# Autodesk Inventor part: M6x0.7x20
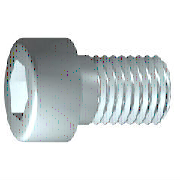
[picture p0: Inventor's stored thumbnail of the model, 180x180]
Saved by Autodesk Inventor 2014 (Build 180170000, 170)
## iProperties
Created: 2009-02
Part Number: M6x0.7x20
Material: 강철, 연강
Description: 6각머리 태핑 나사
Document SubType Name: Modeling
Standard: KS B 1003
Designer: KYOUNG IL JANG
Standards Organization: KS
Language: ko-KR
Size Designation: M 6 x 20
Categories: <MemberInstance><Categories><Category DisplayName="조임쇠" InternalName="e4da775c-781d-43d5-af7c-5136215cf5a6" Mnemonic="FSTN"><Category DisplayName="볼트" InternalN
Density: 7.86 g/cm^3
Mass: 7.48273 g
Surface Area: 7.641 cm^2
Volume: 0.952002 cm^3
Vendor: CBT Solutions
Appearance: 연마 - 진회색
Company: 한국ATC센터
IsCustomPart: 1
Author: KYOUNG IL JANG
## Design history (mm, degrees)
sketch "스케치1"
  geometry: L1 (-1.333, 0)-(20, 0); L2 (20, 0)-(20, 3); L3 (20, 3)-(2.5, 3); L4 (2.5, 3)-(1.886, 3); L5 (1.886, 3)-(0, 3); L6 (0, 3)-(0, 5); L7 (0, 5)-(-6, 5); L8 (-6, 5)-(-6, 2.887); L9 (-6, 2.887)-(-3, 2.887); L10 (-3, 2.887)-(-1.333, 0); L11 (-11.2, 0)-(25.2, 0) reference; L12 (0, -1)-(0, 6) reference; L13 (2.5, 3)-(0, 3)
  constraints: 22 end point, 6 parallel, 2 collinear, 2 perpendicular, 1 horizontal, 1 point on line
  dimensions: "d1" = 17.5 distance from line of L3.end L2 (= GEL); "d2" = 0.61355 distance of L4.end L3.end (computed from GAL); "d3" = 6 distance between parallel lines of L8 L6 (= KOH); "d4" = 3 distance of L8.end L9.end (= INTI); "d5" = 60 deg angle of L10 L1; "d6" = 6 diameter of L3 L1 (= GD); "d7" = 6 diameter of L5 L1 (= BDM); "d8" = 5.7735 diameter of L9 L1 (= 1.1547 x SW); "d9" = 10 diameter of L7 L1 (= KOD); "d26" = 20 distance between parallel lines of L12 L2 (= NLG)
revolve "본체" sketch "스케치1" stored, may be unused: angle "d10" = 90 deg
sketch "스케치2"
  geometry: L1 (0, -7)-(0, 7) reference; L2 (-7, 0)-(7, 0) reference; L3 (2.887, 0)-(1.443, -2.5); L4 (1.443, -2.5)-(-1.443, -2.5); L5 (-1.443, -2.5)-(-2.887, 0); L6 (-2.887, 0)-(-1.443, 2.5); L7 (-1.443, 2.5)-(1.443, 2.5); L8 (1.443, 2.5)-(2.887, 0); 2 further points
  constraints: 12 end point, 1 coincident, 1 horizontal alignment, 1 point on line, 12 other
extrude "슬롯" join sketch "스케치2" stored distance "d11" = 10; taper "d12" = 0 deg
workplane "Work Plane1"
fillet "Fillet2" dims "d30" = 0.1 (= R)
body "Solid1"
fillet "모깎기1" dims "d17" = 0.6 (= RR)
feature "스레드" dims "d13" = 17.5 (= GEL), "d14" = 0
chamfer "모따기1" distance "d15" = 0.61345 (= -0.5 x SPD + 0.5 x GD); stored, may be unused: second distance "d16" = 0.61345 (= GUL), angle "d27" = 45 deg
other parameters: "GD" = 6 (= NND) [user parameter; used in 2 equation terms], "NLG" = 20 [user parameter; used in 1 equation term], "GEL" = 17.5 [user parameter; used in 2 equation terms], "KOD" = 10 [user parameter; used in 1 equation term], "KOH" = 6 [user parameter; used in 1 equation term], "INTI" = 3 [user parameter; used in 1 equation term], "GAL" = 0.61345 (= 0.61345 x PTC) [user parameter; used in 1 equation term], "GUL" = 0.61345 (= 0.61345 x PTC) [user parameter; used in 1 equation term], "BDM" = 6 (= NND) [user parameter; used in 1 equation term], "SW" = 5 [user parameter; used in 2 equation terms], "RR" = 0.6 [user parameter; used in 1 equation term], "SPD" = 4.7731 (= NND - 1.2269 x PTC) [user parameter; used in 1 equation term], "d19" = 0, "d28" = 0, "d29" = 0, "R" = 0.1 [user parameter; used in 1 equation term], "PHH" = 0.25 [user parameter], "GD1" = 4.7731 (= THREADDIA - 1.2269 x PTC) [user parameter], "THREADDIA" = 6 [user parameter; used in 1 equation term], "FAWI" = 45 deg [user parameter], "PTC" = 1 [user parameter; used in 5 equation terms], "NND" = 6 [user parameter; used in 3 equation terms], "TOA" = 30 deg [user parameter], "E0" = 5.775 (= 1.155 x SW) [user parameter]
